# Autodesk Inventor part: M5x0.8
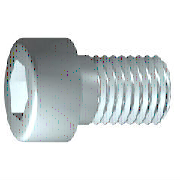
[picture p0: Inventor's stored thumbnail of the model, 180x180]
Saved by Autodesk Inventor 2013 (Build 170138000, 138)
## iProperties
IsCustomPart: 0
Manager: KYOUNG IL JANG
Company: 한국ATC센터
Created: 2009-02
Part Number: M5x0.8
Material: Steel, Mild
Description: 6각머리 태핑 나사
Document SubType Name: Modeling
Standard: KS B 1003
Standards Organization: KS
Language: ko-KR
Size Designation: M 5 x 20
Categories: <MemberInstance><Categories><Category DisplayName="조임쇠" InternalName="e4da775c-781d-43d5-af7c-5136215cf5a6" Mnemonic="FSTN"><Category DisplayName="볼트" InternalN
Density: 1 g/cm^3
Checked By: KYOUNG IL JANG
Vendor: CBT Solutions
Designer: KYOUNG IL JANG
Author: KYOUNG IL JANG
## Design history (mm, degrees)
sketch "스케치1"
  geometry: L1 (-1.167, 0)-(20, 0); L2 (20, 0)-(20, 2.5); L3 (20, 2.5)-(2, 2.5); L4 (2, 2.5)-(1.509, 2.5); L5 (1.509, 2.5)-(0, 2.5); L6 (0, 2.5)-(0, 4.25); L7 (0, 4.25)-(-5, 4.25); L8 (-5, 4.25)-(-5, 2.309); L9 (-5, 2.309)-(-2.5, 2.309); L10 (-2.5, 2.309)-(-1.167, 0); L11 (-10, 0)-(25, 0) reference; L12 (0, -0.85)-(0, 5.1) reference; L13 (2, 2.5)-(0, 2.5)
  constraints: 22 end point, 6 parallel, 2 collinear, 2 perpendicular, 1 horizontal, 1 point on line
  dimensions: "d1" = 18 distance from line of L3.end L2 (= GEL); "d2" = 0.49086 distance of L4.end L3.end (computed from GAL); "d3" = 5 distance between parallel lines of L8 L6 (= KOH); "d4" = 2.5 distance of L8.end L9.end (= INTI); "d5" = 60 deg angle of L10 L1; "d6" = 5 diameter of L3 L1 (= GD); "d7" = 5 diameter of L5 L1 (= BDM); "d8" = 4.6188 diameter of L9 L1 (= 1.1547 x SW); "d9" = 8.5 diameter of L7 L1 (= KOD); "d26" = 20 distance between parallel lines of L12 L2 (= NLG)
revolve "본체" sketch "스케치1" stored, may be unused: angle "d10" = 90 deg
sketch "스케치2"
  geometry: L1 (0, -5.95)-(0, 5.95) reference; L2 (-5.95, 0)-(5.95, 0) reference; L3 (2.309, 0)-(1.155, -2); L4 (1.155, -2)-(-1.155, -2); L5 (-1.155, -2)-(-2.309, 0); L6 (-2.309, 0)-(-1.155, 2); L7 (-1.155, 2)-(1.155, 2); L8 (1.155, 2)-(2.309, 0); 2 further points
  constraints: 12 end point, 1 coincident, 1 horizontal alignment, 1 point on line, 12 other
extrude "슬롯" join sketch "스케치2" stored distance "d11" = 10; taper "d12" = 0 deg
workplane "Work Plane1"
fillet "Fillet2" dims "d30" = 0.1 (= R)
body "Solid1"
fillet "모깎기1" dims "d17" = 0.5 (= RR)
feature "스레드" dims "d13" = 18 (= GEL), "d14" = 0
chamfer "모따기1" distance "d15" = 0.49076 (= -0.5 x SPD + 0.5 x GD); stored, may be unused: second distance "d16" = 0.49076 (= GUL), angle "d27" = 45 deg
other parameters: "GD" = 5 (= NND) [user parameter; used in 2 equation terms], "NLG" = 20 [user parameter; used in 1 equation term], "GEL" = 18 [user parameter; used in 2 equation terms], "KOD" = 8.5 [user parameter; used in 1 equation term], "KOH" = 5 [user parameter; used in 1 equation term], "INTI" = 2.5 [user parameter; used in 1 equation term], "GAL" = 0.49076 (= 0.61345 x PTC) [user parameter; used in 1 equation term], "GUL" = 0.49076 (= 0.61345 x PTC) [user parameter; used in 1 equation term], "BDM" = 5 (= NND) [user parameter; used in 1 equation term], "SW" = 4 [user parameter; used in 2 equation terms], "RR" = 0.5 [user parameter; used in 1 equation term], "SPD" = 4.01848 (= NND - 1.2269 x PTC) [user parameter; used in 1 equation term], "d19" = 0, "d28" = 0, "d29" = 0, "R" = 0.1 [user parameter; used in 1 equation term], "PHH" = 0.2 [user parameter], "GD1" = 4.01848 (= THREADDIA - 1.2269 x PTC) [user parameter], "THREADDIA" = 5 [user parameter; used in 1 equation term], "FAWI" = 45 deg [user parameter], "TPU" = 12.5 (computed from PTC) [user parameter], "PTC" = 0.8 [user parameter; used in 5 equation terms], "NND" = 5 [user parameter; used in 3 equation terms], "TOA" = 30 deg [user parameter], "E0" = 4.62 (= 1.155 x SW) [user parameter]
